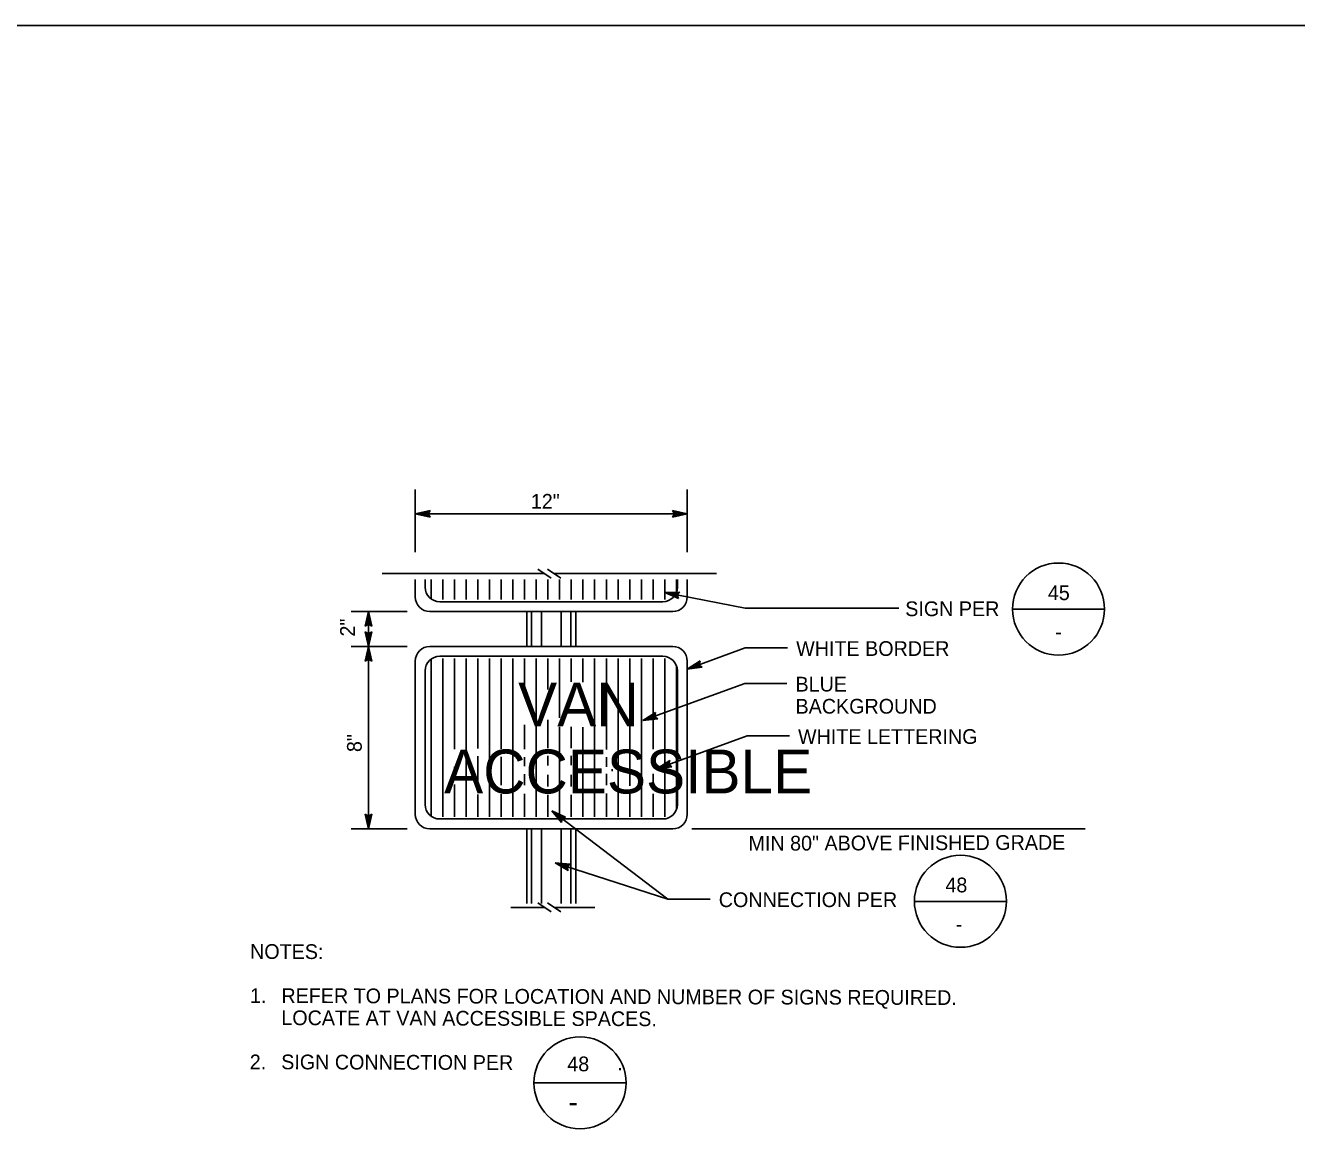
# Model space of a CAD drawing. Extents: x -121933 to -117742, y -103160 to -100084.
# Drawn here: x -118856 to -118338, y -101578 to -101122 of the extents above; entities that cross this region are included whole.
import ezdxf

# ---------------------------------------------------------------- set-up
doc = ezdxf.new("R2010")
doc.units = 0
for name, color, linetype in [('57 Undefined', 7, 'Continuous'), ('60 Nongeo Data', 7, 'Continuous'), ('Control (1)', 7, 'Continuous'), ('Default', 7, 'Continuous'), ('G-MARK', 7, 'Continuous'), ('G-TEXT', 7, 'Continuous'), ('Misc CnstDet(22)', 7, 'Continuous'), ('Sheet Format(10)', 7, 'Continuous')]:
    doc.layers.add(name, color=color, linetype=linetype)

msp = doc.modelspace()

# ---------------------------------------------------------------- linework, layer by layer
at = {"layer": '60 Nongeo Data'}
for p, q in [((-118697.1, -101355.28), (-118697.1, -101348.1)), ((-118693.09, -101351.22), (-118693.09, -101348.1)), ((-118690.71, -101355.98), (-118690.71, -101348.1)), ((-118685.95, -101356.25), (-118685.95, -101348.1)), ((-118681.19, -101356.25), (-118681.19, -101348.1)), ((-118676.43, -101356.25), (-118676.43, -101348.1)), ((-118671.67, -101356.25), (-118671.67, -101348.1)), ((-118666.91, -101356.25), (-118666.91, -101348.1)), ((-118662.15, -101356.25), (-118662.15, -101348.1)), ((-118657.39, -101356.25), (-118657.39, -101348.1)), ((-118652.63, -101356.25), (-118652.63, -101348.1)), ((-118647.87, -101356.25), (-118647.87, -101348.1)), ((-118643.11, -101356.25), (-118643.11, -101348.1)), ((-118638.35, -101356.25), (-118638.35, -101348.1)), ((-118633.59, -101356.25), (-118633.59, -101348.1)), ((-118628.83, -101356.25), (-118628.83, -101348.1)), ((-118624.07, -101356.25), (-118624.07, -101348.1)), ((-118619.31, -101356.25), (-118619.31, -101348.1)), ((-118614.55, -101356.25), (-118614.55, -101348.1)), ((-118609.79, -101356.25), (-118609.79, -101348.1)), ((-118605.03, -101356.25), (-118605.03, -101348.1)), ((-118600.27, -101356.25), (-118600.27, -101348.1)), ((-118595.51, -101356.25), (-118595.51, -101348.1)), ((-118590.75, -101353.34), (-118590.75, -101348.1)), ((-118590.36, -101351.22), (-118590.36, -101348.1)), ((-118586.34, -101355.23), (-118586.34, -101348.1)), ((-118596.31, -101357.17), (-118687.14, -101357.17)), ((-118592.29, -101361.18), (-118691.15, -101361.18)), ((-118691.15, -101375.39), (-118592.29, -101375.39)), ((-118697.1, -101443.81), (-118697.1, -101381.29)), ((-118690.71, -101444.5), (-118690.71, -101380.59)), ((-118687.14, -101379.4), (-118596.31, -101379.4)), ((-118685.95, -101444.78), (-118685.95, -101380.32)), ((-118681.19, -101417.27), (-118681.19, -101380.32)), ((-118676.43, -101444.78), (-118676.43, -101380.32)), ((-118671.67, -101416.99), (-118671.67, -101380.32)), ((-118666.91, -101444.78), (-118666.91, -101380.32)), ((-118662.15, -101417.13), (-118662.15, -101380.32)), ((-118657.39, -101444.78), (-118657.39, -101380.32)), ((-118652.63, -101395.1), (-118652.63, -101380.32)), ((-118647.87, -101444.78), (-118647.87, -101380.32)), ((-118643.11, -101392.92), (-118643.11, -101380.32)), ((-118638.35, -101404.43), (-118638.35, -101380.32)), ((-118633.59, -101389.8), (-118633.59, -101380.32)), ((-118628.83, -101390), (-118628.83, -101380.32)), ((-118624.07, -101444.78), (-118624.07, -101380.32)), ((-118619.31, -101417.35), (-118619.31, -101380.32)), ((-118614.55, -101444.78), (-118614.55, -101380.32)), ((-118609.79, -101432.14), (-118609.79, -101380.32)), ((-118605.03, -101444.78), (-118605.03, -101380.32)), ((-118600.27, -101417.3), (-118600.27, -101380.32)), ((-118595.51, -101444.78), (-118595.51, -101380.32)), ((-118586.34, -101443.76), (-118586.34, -101381.34)), ((-118693.09, -101439.74), (-118693.09, -101385.35)), ((-118590.75, -101441.87), (-118590.75, -101383.23)), ((-118590.36, -101439.74), (-118590.36, -101385.35)), ((-118652.63, -101417.27), (-118652.63, -101407.35)), ((-118643.11, -101416.81), (-118643.11, -101405.24)), ((-118638.35, -101444.78), (-118638.35, -101408.1)), ((-118633.59, -101416.85), (-118633.59, -101408.1)), ((-118628.83, -101444.78), (-118628.83, -101408.3)), ((-118671.67, -101432.4), (-118671.67, -101420.1)), ((-118662.15, -101431.95), (-118662.15, -101420.31)), ((-118652.63, -101424.24), (-118652.63, -101420.53)), ((-118643.11, -101423.92), (-118643.11, -101420)), ((-118633.59, -101423.75), (-118633.59, -101419.93)), ((-118619.31, -101424.47), (-118619.31, -101420.47)), ((-118600.27, -101424.2), (-118600.27, -101420.46)), ((-118681.19, -101428.44), (-118681.19, -101424.38)), ((-118652.63, -101431.95), (-118652.63, -101427.39)), ((-118643.11, -101432.44), (-118643.11, -101427.67)), ((-118633.59, -101432.51), (-118633.59, -101427.67)), ((-118619.31, -101431.97), (-118619.31, -101427.34)), ((-118616.93, -101426.22), (-118616.93, -101425.34)), ((-118600.27, -101431.95), (-118600.27, -101427.29)), ((-118681.19, -101444.78), (-118681.19, -101431.63)), ((-118671.67, -101444.78), (-118671.67, -101435.77)), ((-118662.15, -101444.78), (-118662.15, -101435.63)), ((-118652.63, -101444.78), (-118652.63, -101435.38)), ((-118643.11, -101444.78), (-118643.11, -101435.87)), ((-118633.59, -101444.78), (-118633.59, -101435.8)), ((-118619.31, -101444.78), (-118619.31, -101435.29)), ((-118609.79, -101444.78), (-118609.79, -101435.33)), ((-118600.27, -101444.78), (-118600.27, -101435.38)), ((-118596.31, -101445.69), (-118687.14, -101445.69)), ((-118592.29, -101449.71), (-118691.15, -101449.71))]:
    msp.add_line(p, q, dxfattribs=at)
for centre, start, end in [((-118691.15, -101355.23), 180, 270), ((-118687.14, -101351.22), 180, 270), ((-118596.31, -101351.22), 270, 0), ((-118592.29, -101355.23), 270, 0), ((-118691.15, -101381.34), 90, 180), ((-118592.29, -101381.34), 0, 90), ((-118687.14, -101385.35), 90, 180), ((-118596.31, -101385.35), 0, 90), ((-118687.14, -101439.75), 180, 270), ((-118596.31, -101439.75), 270, 0), ((-118691.15, -101443.76), 180, 270), ((-118592.29, -101443.76), 270, 0)]:
    msp.add_arc(centre, 5.95, start, end, dxfattribs=at)
at = {"layer": 'Control (1)'}
for p, q in [((-118454.11, -101360.21), (-118416.41, -101360.21)), ((-118494.05, -101479.28), (-118456.35, -101479.28)), ((-118648.97, -101553.26), (-118611.27, -101553.26))]:
    msp.add_line(p, q, dxfattribs=at)
for centre in [(-118435.16, -101360.16), (-118475.1, -101479.23), (-118630.02, -101553.21)]:
    msp.add_circle(centre, 18.75, dxfattribs=at)
at = {"layer": 'Default'}
msp.add_lwpolyline([(-119542.38, -101122.36), (-117742.38, -101122.36), (-117742.38, -102572.36), (-119542.38, -102572.36)], close=True, dxfattribs=at)
at = {"layer": 'G-MARK'}
for p, q in [((-118586.34, -101321.39), (-118697.1, -101321.39)), ((-118716.15, -101361.18), (-118716.15, -101375.39)), ((-118716.15, -101375.39), (-118716.15, -101449.71))]:
    msp.add_line(p, q, dxfattribs=at)
for points in [[(-118595.55, -101353.48), (-118562.71, -101359.77), (-118500.21, -101359.77)], [(-118586.34, -101384.6), (-118562.71, -101375.97), (-118545.52, -101375.97)], [(-118604.46, -101405.63), (-118562.97, -101390.49), (-118545.78, -101390.49)], [(-118598.68, -101425.22), (-118561.96, -101411.82), (-118544.77, -101411.82)], [(-118641.47, -101442.36), (-118594.23, -101478.31), (-118577.04, -101478.31)], [(-118640.18, -101463.52), (-118594.23, -101478.31), (-118577.04, -101478.31)]]:
    msp.add_lwpolyline(points, dxfattribs=at)
at = {"layer": 'G-TEXT'}
for p, q in [((-118697.1, -101321.39), (-118691.1, -101320.06)), ((-118691.1, -101322.73), (-118697.1, -101321.39)), ((-118697.1, -101321.39), (-118697.1, -101321.39)), ((-118691.32, -101322.38), (-118695.72, -101321.39)), ((-118695.71, -101321.39), (-118691.34, -101320.42)), ((-118694.34, -101321.39), (-118691.51, -101320.77)), ((-118691.55, -101322.02), (-118694.34, -101321.39)), ((-118692.96, -101321.4), (-118691.75, -101321.13)), ((-118691.73, -101321.67), (-118692.96, -101321.4)), ((-118691.1, -101320.06), (-118691.9, -101321.39)), ((-118691.9, -101321.39), (-118691.1, -101322.73)), ((-118691.1, -101320.06), (-118691.1, -101320.06)), ((-118691.1, -101322.73), (-118691.1, -101322.73)), ((-118591.54, -101321.39), (-118592.34, -101320.05)), ((-118592.34, -101320.05), (-118592.34, -101320.05)), ((-118592.34, -101320.05), (-118586.34, -101321.39)), ((-118586.34, -101321.39), (-118592.34, -101322.72)), ((-118592.34, -101322.72), (-118591.54, -101321.39)), ((-118592.34, -101322.72), (-118592.34, -101322.72)), ((-118592.13, -101320.41), (-118587.72, -101321.39)), ((-118587.74, -101321.4), (-118592.11, -101322.36)), ((-118589.11, -101321.39), (-118591.93, -101322.02)), ((-118591.89, -101320.77), (-118589.11, -101321.39)), ((-118591.72, -101321.12), (-118590.49, -101321.39)), ((-118590.49, -101321.39), (-118591.7, -101321.66)), ((-118586.34, -101321.39), (-118586.34, -101321.39)), ((-118595.55, -101353.48), (-118589.41, -101353.3)), ((-118589.91, -101355.92), (-118595.55, -101353.48)), ((-118595.55, -101353.48), (-118595.55, -101353.48)), ((-118590.06, -101355.53), (-118594.2, -101353.74)), ((-118594.18, -101353.74), (-118589.71, -101353.61)), ((-118592.84, -101354), (-118589.95, -101353.92)), ((-118590.22, -101355.14), (-118592.84, -101354)), ((-118591.48, -101354.26), (-118590.24, -101354.23)), ((-118590.33, -101354.76), (-118591.48, -101354.26)), ((-118589.41, -101353.3), (-118590.44, -101354.46)), ((-118590.44, -101354.46), (-118589.91, -101355.92)), ((-118589.41, -101353.3), (-118589.41, -101353.3)), ((-118589.91, -101355.92), (-118589.91, -101355.92)), ((-118717.49, -101367.18), (-118716.15, -101361.18)), ((-118717.14, -101366.97), (-118716.15, -101362.56)), ((-118716.78, -101366.73), (-118716.15, -101363.95)), ((-118716.43, -101366.56), (-118716.16, -101365.33)), ((-118716.16, -101365.33), (-118715.89, -101366.54)), ((-118716.15, -101361.18), (-118716.15, -101361.18)), ((-118716.15, -101361.18), (-118714.82, -101367.18)), ((-118716.15, -101362.57), (-118715.18, -101366.95)), ((-118716.15, -101363.95), (-118715.53, -101366.77)), ((-118716.15, -101366.38), (-118717.49, -101367.18)), ((-118717.49, -101367.18), (-118717.49, -101367.18)), ((-118716.15, -101375.39), (-118717.48, -101369.39)), ((-118717.48, -101369.39), (-118717.48, -101369.39)), ((-118717.48, -101369.39), (-118716.15, -101370.19)), ((-118716.16, -101374), (-118717.12, -101369.62)), ((-118716.15, -101372.63), (-118716.78, -101369.8)), ((-118716.15, -101371.24), (-118716.42, -101370.04)), ((-118714.82, -101367.18), (-118716.15, -101366.38)), ((-118716.15, -101370.19), (-118714.81, -101369.39)), ((-118714.81, -101369.39), (-118716.15, -101375.39)), ((-118715.17, -101369.6), (-118716.15, -101374.01)), ((-118715.53, -101369.84), (-118716.15, -101372.63)), ((-118715.87, -101370.01), (-118716.15, -101371.24)), ((-118714.82, -101367.18), (-118714.82, -101367.18)), ((-118714.81, -101369.39), (-118714.81, -101369.39)), ((-118717.49, -101381.39), (-118716.15, -101375.39)), ((-118716.15, -101375.39), (-118716.15, -101375.39)), ((-118716.15, -101375.39), (-118714.82, -101381.39)), ((-118716.15, -101375.39), (-118716.15, -101375.39)), ((-118716.15, -101380.59), (-118717.49, -101381.39)), ((-118717.49, -101381.39), (-118717.49, -101381.39)), ((-118717.14, -101381.17), (-118716.15, -101376.77)), ((-118716.78, -101380.94), (-118716.15, -101378.15)), ((-118716.43, -101380.76), (-118716.16, -101379.53)), ((-118716.16, -101379.53), (-118715.89, -101380.74)), ((-118716.15, -101376.78), (-118715.18, -101381.15)), ((-118716.15, -101378.15), (-118715.53, -101380.98)), ((-118714.82, -101381.39), (-118716.15, -101380.59)), ((-118714.82, -101381.39), (-118714.82, -101381.39)), ((-118586.34, -101384.6), (-118581.16, -101381.29)), ((-118581.16, -101381.29), (-118581.46, -101382.81)), ((-118581.16, -101381.29), (-118581.16, -101381.29)), ((-118580.25, -101383.8), (-118586.34, -101384.6)), ((-118586.34, -101384.6), (-118586.34, -101384.6)), ((-118580.57, -101383.54), (-118585.05, -101384.12)), ((-118585.04, -101384.12), (-118581.26, -101381.71)), ((-118583.75, -101383.65), (-118581.31, -101382.1)), ((-118580.92, -101383.28), (-118583.75, -101383.65)), ((-118582.45, -101383.18), (-118581.41, -101382.51)), ((-118581.2, -101383.02), (-118582.45, -101383.18)), ((-118581.46, -101382.81), (-118580.25, -101383.8)), ((-118580.25, -101383.8), (-118580.25, -101383.8)), ((-118604.46, -101405.63), (-118599.28, -101402.33)), ((-118598.36, -101404.84), (-118604.46, -101405.63)), ((-118604.46, -101405.63), (-118604.46, -101405.63)), ((-118598.69, -101404.58), (-118603.16, -101405.16)), ((-118603.15, -101405.15), (-118599.38, -101402.75)), ((-118601.86, -101404.69), (-118599.42, -101403.13)), ((-118599.03, -101404.32), (-118601.86, -101404.69)), ((-118600.57, -101404.22), (-118599.52, -101403.55)), ((-118599.32, -101404.05), (-118600.57, -101404.22)), ((-118599.28, -101402.33), (-118599.57, -101403.85)), ((-118599.57, -101403.85), (-118598.36, -101404.84)), ((-118599.28, -101402.33), (-118599.28, -101402.33)), ((-118598.36, -101404.84), (-118598.36, -101404.84)), ((-118598.68, -101425.22), (-118593.5, -101421.92)), ((-118597.37, -101424.75), (-118593.59, -101422.34)), ((-118596.08, -101424.28), (-118593.64, -101422.72)), ((-118593.5, -101421.92), (-118593.79, -101423.44)), ((-118593.5, -101421.92), (-118593.5, -101421.92)), ((-118592.58, -101424.43), (-118598.68, -101425.22)), ((-118598.68, -101425.22), (-118598.68, -101425.22)), ((-118592.91, -101424.17), (-118597.38, -101424.75)), ((-118593.25, -101423.91), (-118596.08, -101424.28)), ((-118594.78, -101423.81), (-118593.74, -101423.14)), ((-118593.53, -101423.65), (-118594.78, -101423.81)), ((-118593.79, -101423.44), (-118592.58, -101424.43)), ((-118592.58, -101424.43), (-118592.58, -101424.43)), ((-118637.51, -101447.06), (-118641.47, -101442.36)), ((-118641.47, -101442.36), (-118641.47, -101442.36)), ((-118641.47, -101442.36), (-118635.89, -101444.93)), ((-118637.46, -101446.64), (-118640.37, -101443.19)), ((-118640.36, -101443.2), (-118636.3, -101445.08)), ((-118716.15, -101449.71), (-118717.48, -101443.71)), ((-118717.48, -101443.71), (-118717.48, -101443.71)), ((-118717.48, -101443.71), (-118716.15, -101444.51)), ((-118716.16, -101448.32), (-118717.12, -101443.95)), ((-118716.15, -101446.95), (-118716.78, -101444.12)), ((-118716.15, -101445.57), (-118716.42, -101444.36)), ((-118716.15, -101444.51), (-118714.81, -101443.71)), ((-118714.81, -101443.71), (-118716.15, -101449.71)), ((-118715.17, -101443.93), (-118716.15, -101448.33)), ((-118715.53, -101444.16), (-118716.15, -101446.95)), ((-118715.87, -101444.34), (-118716.15, -101445.57)), ((-118714.81, -101443.71), (-118714.81, -101443.71)), ((-118637.43, -101446.22), (-118639.27, -101444.03)), ((-118639.27, -101444.03), (-118636.65, -101445.24)), ((-118637.36, -101445.83), (-118638.18, -101444.87)), ((-118638.18, -101444.87), (-118637.05, -101445.39)), ((-118637.33, -101445.51), (-118637.51, -101447.06)), ((-118637.51, -101447.06), (-118637.51, -101447.06)), ((-118635.89, -101444.93), (-118637.33, -101445.51)), ((-118635.89, -101444.93), (-118635.89, -101444.93)), ((-118716.15, -101449.71), (-118716.15, -101449.71)), ((-118634.87, -101466.63), (-118640.18, -101463.52)), ((-118640.18, -101463.52), (-118640.18, -101463.52)), ((-118640.18, -101463.52), (-118634.06, -101464.09)), ((-118634.97, -101466.23), (-118638.86, -101463.94)), ((-118638.85, -101463.94), (-118634.39, -101464.36)), ((-118634.06, -101464.09), (-118635.23, -101465.11)), ((-118634.06, -101464.09), (-118634.06, -101464.09)), ((-118635.08, -101465.81), (-118637.55, -101464.37)), ((-118637.55, -101464.37), (-118634.66, -101464.64)), ((-118635.15, -101465.43), (-118636.23, -101464.79)), ((-118636.23, -101464.79), (-118635, -101464.91)), ((-118635.23, -101465.11), (-118634.87, -101466.63)), ((-118634.87, -101466.63), (-118634.87, -101466.63))]:
    msp.add_line(p, q, dxfattribs=at)
at = {"layer": 'Misc CnstDet(22)'}
for p, q in [((-118697.1, -101311.47), (-118697.1, -101336.95)), ((-118586.34, -101311.47), (-118586.34, -101336.95)), ((-118647.17, -101343.89), (-118641.77, -101347.56)), ((-118643.28, -101343.89), (-118637.88, -101347.56)), ((-118710.65, -101345.73), (-118644.47, -101345.73)), ((-118640.58, -101345.73), (-118574.4, -101345.73)), ((-118723.28, -101361.18), (-118700.39, -101361.18)), ((-118651.72, -101361.18), (-118651.72, -101375.39)), ((-118649.72, -101361.18), (-118649.72, -101375.39)), ((-118645.72, -101361.18), (-118645.72, -101375.39)), ((-118637.72, -101361.18), (-118637.72, -101375.39)), ((-118633.72, -101361.18), (-118633.72, -101375.39)), ((-118631.72, -101361.18), (-118631.72, -101375.39)), ((-118723.28, -101375.39), (-118700.39, -101375.39)), ((-118723.28, -101375.39), (-118700.39, -101375.39)), ((-118723.28, -101449.71), (-118700.39, -101449.71)), ((-118651.72, -101449.71), (-118651.72, -101480.19)), ((-118649.72, -101449.71), (-118649.72, -101480.19)), ((-118645.72, -101449.71), (-118645.72, -101480.19)), ((-118637.72, -101449.71), (-118637.72, -101480.19)), ((-118633.72, -101449.71), (-118633.72, -101480.19)), ((-118631.72, -101449.71), (-118631.72, -101480.19)), ((-118584.52, -101449.71), (-118424.31, -101449.71)), ((-118658.26, -101481.76), (-118644.47, -101481.76)), ((-118647.17, -101479.92), (-118641.77, -101483.59)), ((-118643.28, -101479.92), (-118637.88, -101483.59)), ((-118640.58, -101481.76), (-118623.93, -101481.76))]:
    msp.add_line(p, q, dxfattribs=at)

# ---------------------------------------------------------------- texts
at = {"layer": '57 Undefined'}
for s, p in [('SIGN PER', (-118497.58, -101363.05)), ('WHITE BORDER', (-118542, -101379.25)), ('BLUE', (-118542.26, -101393.77)), ('BACKGROUND', (-118542.26, -101402.77)), ('WHITE LETTERING', (-118541.25, -101415.11)), ('CONNECTION PER', (-118573.52, -101481.59))]:
    msp.add_text(s, height=6, dxfattribs=at).set_placement(p)
for s, rotation, p in [('MIN 80" ABOVE FINISHED GRADE', 0.168, (-118561.4, -101458.61)), ('NOTES:  ', 359.832, (-118764.4, -101502.67)), ('1.', 359.832, (-118764.45, -101520.67)), ('REFER TO PLANS FOR LOCATION AND NUMBER OF SIGNS REQUIRED. ', 359.832, (-118751.64, -101520.67)), ('LOCATE AT VAN ACCESSIBLE SPACES.', 359.832, (-118751.67, -101529.67)), ('2.', 359.832, (-118764.53, -101547.67)), ('SIGN CONNECTION PER                   .', 359.832, (-118751.72, -101547.67))]:
    msp.add_text(s, height=6, rotation=rotation, dxfattribs=at).set_placement(p)
at = {"layer": '60 Nongeo Data'}
for s, p in [('VAN', (-118655.23, -101407.97)), ('ACCESSIBLE', (-118685.37, -101435.27))]:
    msp.add_text(s, height=17.849, dxfattribs=at).set_placement(p)
at = {"layer": 'Control (1)'}
msp.add_text('-', height=8.75, dxfattribs=at).set_placement((-118634.74, -101565.25))
at = {"layer": 'Misc CnstDet(22)'}
for s, rotation, p in [('12"', 0.168, (-118650.04, -101319.28)), ('2"', 90.168, (-118721.72, -101371.35)), ('8"', 90.168, (-118718.91, -101418.42))]:
    msp.add_text(s, height=6, rotation=rotation, dxfattribs=at).set_placement(p)
at = {"layer": 'Sheet Format(10)'}
for s, p in [('45', (-118439.49, -101356.52)), ('-', (-118436.53, -101372.41)), ('48', (-118481.22, -101475.59)), ('-', (-118477.02, -101491.49)), ('48', (-118635.21, -101548.5))]:
    msp.add_text(s, height=6, dxfattribs=at).set_placement(p)

doc.saveas('drawing.dxf')
